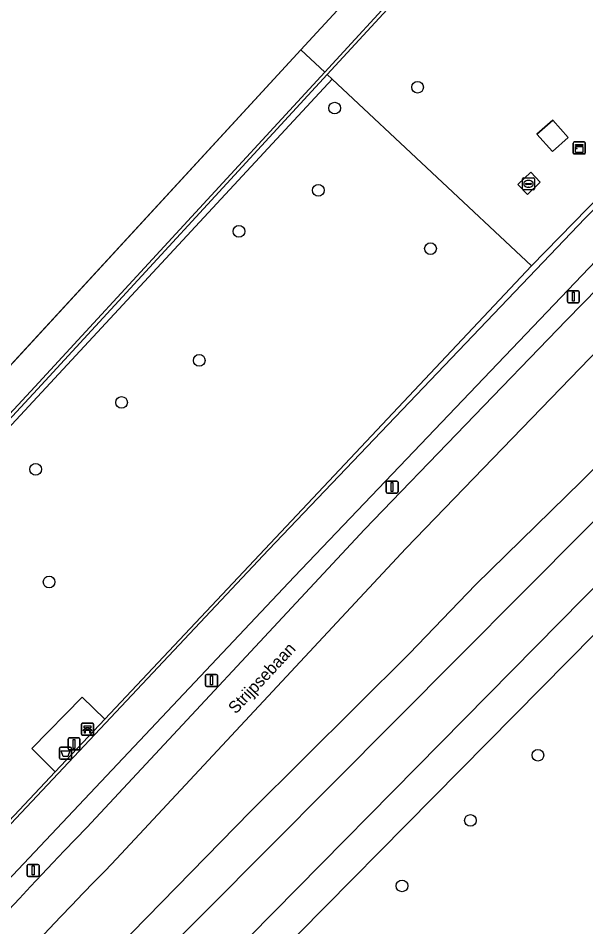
# Model space of a CAD drawing. Extents: x 155640 to 156811, y 382821 to 384049.
# Drawn here: x 156314.4 to 156361.8, y 383250.2 to 383326 of the extents above; entities that cross this region are included whole.
import ezdxf

# ---------------------------------------------------------------- set-up
doc = ezdxf.new("R2010")
doc.units = 0
for name, color, linetype in [('IMGEO_Afvalbak', 7, 'Continuous'), ('IMGEO_Bank', 7, 'Continuous'), ('IMGEO_Berm_groen', 7, 'Continuous'), ('IMGEO_Boom', 7, 'Continuous'), ('IMGEO_Fietspad_gesloten', 7, 'Continuous'), ('IMGEO_Groenvoorziening', 7, 'Continuous'), ('IMGEO_Haag', 7, 'Continuous'), ('IMGEO_Hek', 7, 'Continuous'), ('IMGEO_Kast', 7, 'Continuous'), ('IMGEO_Lichtmast', 7, 'Continuous'), ('IMGEO_Oever', 7, 'Continuous'), ('IMGEO_Openbare_ruimte_label', 7, 'Continuous'), ('IMGEO_Pand', 7, 'Continuous'), ('IMGEO_Rioolput', 7, 'Continuous'), ('IMGEO_Verkeersbordpaal', 7, 'Continuous'), ('IMGEO_Voetpad_gesloten', 7, 'Continuous'), ('IMGEO_Waterloop', 7, 'Continuous')]:
    doc.layers.add(name, color=color, linetype=linetype)

msp = doc.modelspace()

# ---------------------------------------------------------------- linework, layer by layer
at = {"layer": 'IMGEO_Afvalbak'}
for p, q in [((156317.874, 383264.249), (156317.874, 383265.049)), ((156317.874, 383265.049), (156317.874, 383264.249)), ((156317.974, 383265.149), (156318.764, 383265.149)), ((156318.764, 383265.149), (156317.974, 383265.149)), ((156318.864, 383265.049), (156318.864, 383264.249)), ((156318.864, 383264.249), (156318.864, 383265.049)), ((156318.764, 383264.149), (156317.974, 383264.149)), ((156317.974, 383264.149), (156318.764, 383264.149))]:
    msp.add_line(p, q, dxfattribs=at)
msp.add_lwpolyline([(156318.017, 383264.863), (156318.721, 383264.863), (156318.572, 383264.393), (156318.166, 383264.393), (156318.017, 383264.863)], dxfattribs=at)
for centre, start, end in [((156317.974, 383265.049), 90, 180), ((156317.974, 383265.049), 90, 180), ((156318.764, 383265.049), 0, 90), ((156318.764, 383265.049), 360, 90), ((156317.974, 383264.249), 180, 270), ((156317.974, 383264.249), 180, 270), ((156318.764, 383264.249), 270, 0), ((156318.764, 383264.249), 270, 0)]:
    msp.add_arc(centre, 0.1, start, end, dxfattribs=at)
at = {"layer": 'IMGEO_Bank'}
for p, q in [((156319.7, 383266.232), (156319.7, 383267.073)), ((156319.7, 383267.073), (156319.7, 383266.232)), ((156319.775, 383267.157), (156320.616, 383267.157)), ((156320.616, 383267.157), (156319.775, 383267.157)), ((156320.7, 383267.082), (156320.7, 383266.241)), ((156320.7, 383266.241), (156320.7, 383267.082)), ((156320.397, 383266.555), (156320.004, 383266.555)), ((156320.009, 383266.663), (156320.009, 383266.769)), ((156320.053, 383266.769), (156320.053, 383266.663)), ((156320.341, 383266.775), (156320.059, 383266.775)), ((156320.059, 383266.657), (156320.341, 383266.657)), ((156320.347, 383266.663), (156320.347, 383266.769)), ((156320.391, 383266.769), (156320.391, 383266.663)), ((156320.625, 383266.157), (156319.784, 383266.157)), ((156319.784, 383266.157), (156320.625, 383266.157))]:
    msp.add_line(p, q, dxfattribs=at)
for points in [[(156319.947, 383266.555), (156319.805, 383266.555), (156319.917, 383266.657), (156320.003, 383266.657)], [(156320.003, 383266.775), (156319.917, 383266.775), (156319.917, 383266.936), (156320.48, 383266.936), (156320.48, 383266.775), (156320.397, 383266.775)], [(156319.997, 383266.548), (156319.997, 383266.341), (156319.954, 383266.341), (156319.954, 383266.548)], [(156320.397, 383266.657), (156320.48, 383266.657), (156320.592, 383266.555), (156320.453, 383266.555)], [(156320.447, 383266.548), (156320.447, 383266.341), (156320.403, 383266.341), (156320.403, 383266.548)]]:
    msp.add_lwpolyline(points, dxfattribs=at)
for centre, radius, start, end in [((156319.778, 383267.079), 0.0779, 92.4484, 184.28452), ((156319.778, 383267.079), 0.0779, 92.4484, 184.28452), ((156320.622, 383267.079), 0.0779, 2.4484, 94.28452), ((156320.622, 383267.079), 0.0779, 2.4484, 94.28452), ((156319.947, 383266.548), 0.00671, 2.89567, 87.10433), ((156320.004, 383266.548), 0.00671, 92.89567, 177.10433), ((156320.002, 383266.768), 0.00671, 2.89567, 87.10433), ((156320.002, 383266.664), 0.00671, 272.89567, 357.10433), ((156320.059, 383266.768), 0.00671, 92.89567, 177.10433), ((156320.059, 383266.664), 0.00671, 182.89567, 267.10433), ((156320.341, 383266.768), 0.00671, 2.89567, 87.10433), ((156320.341, 383266.664), 0.00671, 272.89567, 357.10433), ((156320.398, 383266.768), 0.00671, 92.89567, 177.10433), ((156320.398, 383266.664), 0.00671, 182.89567, 267.10433), ((156320.396, 383266.548), 0.00671, 2.89567, 87.10433), ((156320.453, 383266.548), 0.00671, 92.89567, 177.10433), ((156319.778, 383266.235), 0.0779, 182.4484, 274.28452), ((156319.778, 383266.235), 0.0779, 182.4484, 274.28452), ((156320.622, 383266.235), 0.0779, 272.4484, 4.28452), ((156320.622, 383266.235), 0.0779, 272.4484, 4.28452)]:
    msp.add_arc(centre, radius, start, end, dxfattribs=at)
at = {"layer": 'IMGEO_Berm_groen'}
for points in [[(156381.892, 383325.599), (156381.348, 383325.039), (156380.959, 383324.639), (156363.82, 383307.004), (156337.443, 383279.37), (156311.15, 383251.521)], [(156360.181, 383300.803), (156380.194, 383321.217)], [(156373.432, 383309.293), (156346.778, 383281.729), (156322.635, 383255.833)], [(156320.142, 383258.454), (156343.328, 383283.312), (156360.181, 383300.803)], [(156233.027, 383113.173), (156252.866, 383146.34), (156268.602, 383172.647), (156299.809, 383224.819), (156307.157, 383232.786), (156316.472, 383242.07), (156333.801, 383259.79), (156347.065, 383272.962), (156352.588, 383278.703), (156361.434, 383287.344), (156366.724, 383292.604)]]:
    msp.add_lwpolyline(points, dxfattribs=at)
for centre, radius, start, end in [((156587.608, 382998.357), 373.08, 135.80033, 142.47889), ((156555.245, 383025.413), 327.415, 135.27102, 142.78641)]:
    msp.add_arc(centre, radius, start, end, dxfattribs=at)
at = {"layer": 'IMGEO_Boom'}
for centre in [(156347.751, 383320.225), (156340.835, 383318.484), (156339.472, 383311.623), (156332.842, 383308.2), (156348.832, 383306.757), (156329.527, 383297.433), (156323.046, 383293.927), (156315.877, 383288.344), (156316.998, 383278.946), (156357.798, 383264.485), (156352.165, 383259.047), (156346.453, 383253.585)]:
    msp.add_circle(centre, 0.489, dxfattribs=at)
at = {"layer": 'IMGEO_Fietspad_gesloten'}
for points in [[(156380.194, 383321.217), (156360.181, 383300.803), (156343.328, 383283.312), (156320.142, 383258.454)], [(156322.635, 383255.833), (156346.778, 383281.729), (156373.432, 383309.293), (156378.108, 383314.02)]]:
    msp.add_lwpolyline(points, dxfattribs=at)
for centre, radius, start, end in [((156587.608, 382998.357), 373.08, 135.80033, 142.47889), ((156555.245, 383025.413), 327.415, 135.27102, 142.78641)]:
    msp.add_arc(centre, radius, start, end, dxfattribs=at)
at = {"layer": 'IMGEO_Groenvoorziening'}
for points in [[(156307.679, 383394.347), (156302.123, 383400.705), (156299.359, 383400.927), (156306.65, 383393.611), (156313.765, 383385.402), (156329.371, 383369.364), (156360.098, 383342.127), (156366.667, 383336.304), (156365.54, 383332.038), (156365.287, 383328.46), (156365.66, 383324.427), (156366.576, 383319.504), (156367.747, 383316.069), (156357.254, 383305.321), (156321.635, 383267.495), (156317.51, 383263.114), (156305.054, 383249.887), (156299.88, 383244.1), (156294.909, 383238.207), (156290.182, 383232.037), (156285.682, 383225.699), (156281.371, 383219.262), (156269.6, 383231.099)], [(156308.935, 383253.615), (156335.323, 383281.619), (156361.745, 383309.309), (156379.48, 383327.364), (156380.013, 383327.906), (156380.504, 383328.406), (156379.648, 383329.081), (156379.009, 383329.585), (156369.095, 383337.403), (156363.724, 383341.638)], [(156288.244, 383328.729), (156283.659, 383323.836), (156299.584, 383309.177), (156312.986, 383296.711), (156312.61, 383296.315), (156309.263, 383292.789), (156309.574, 383292.506), (156338.016, 383323.341), (156350.486, 383336.861)], [(156346.883, 383328.534), (156340.219, 383321.277), (156340.634, 383320.888), (156357.254, 383305.321), (156367.747, 383316.069), (156366.576, 383319.504), (156365.66, 383324.427), (156365.287, 383328.46)], [(156269.6, 383231.099), (156263.233, 383237.503), (156340.634, 383320.888), (156340.219, 383321.277), (156316.032, 383295.022), (156259.545, 383234.109), (156254.254, 383228.85), (156241.376, 383245.741), (156226.676, 383261.562), (156226.145, 383261.011), (156229.047, 383257.84)], [(156401.917, 383275.179), (156387.41, 383302.346), (156381.815, 383296.443), (156381.713, 383295.875), (156381.067, 383294.349), (156380.037, 383292.488), (156379.109, 383291.061), (156378.013, 383290.134), (156376.603, 383288.823), (156373.814, 383286.022), (156313.066, 383224.543), (156307.199, 383217.739), (156241.776, 383106.748)]]:
    msp.add_lwpolyline(points, dxfattribs=at)
for points in [[(156303.92, 383385.489), (156304.175, 383385.733), (156292.088, 383397.03), (156288.952, 383393.961), (156316.643, 383368.447), (156350.486, 383336.861), (156338.016, 383323.341), (156340, 383321.482), (156346.651, 383328.741), (156354.938, 383337.785), (156351.749, 383340.767)], [(156340.219, 383321.277), (156346.883, 383328.534), (156346.651, 383328.741), (156340, 383321.482), (156315.812, 383295.226), (156259.528, 383234.533), (156235.771, 383256.436), (156228.393, 383263.345), (156228.185, 383263.129), (156235.566, 383256.217), (156259.545, 383234.109), (156316.032, 383295.022)], [(156315.812, 383295.226), (156340, 383321.482), (156338.016, 383323.341), (156309.574, 383292.506), (156309.479, 383292.403), (156307.563, 383290.326), (156286.105, 383267.166), (156285.653, 383266.679), (156282.79, 383263.589), (156259.014, 383237.928), (156232.367, 383263.357), (156230.326, 383265.146), (156230.078, 383264.903), (156229.968, 383265.006), (156229.248, 383264.232), (156228.393, 383263.345), (156235.771, 383256.436), (156259.528, 383234.533)], [(156321.635, 383267.495), (156357.254, 383305.321), (156340.634, 383320.888), (156263.233, 383237.503), (156269.6, 383231.099), (156281.371, 383219.262), (156285.682, 383225.699), (156290.182, 383232.037), (156294.909, 383238.207), (156299.88, 383244.1), (156305.054, 383249.887), (156317.51, 383263.114), (156315.563, 383265.05), (156319.758, 383269.341)], [(156359.03, 383317.477), (156360.316, 383316.034), (156359.003, 383314.864), (156357.717, 383316.307)], [(156357.2, 383313.134), (156357.996, 383312.308), (156356.925, 383311.275), (156356.129, 383312.101)]]:
    msp.add_lwpolyline(points, close=True, dxfattribs=at)
at = {"layer": 'IMGEO_Haag'}
msp.add_lwpolyline([(156340.219, 383321.277), (156346.883, 383328.534), (156346.651, 383328.741), (156340, 383321.482), (156315.812, 383295.226), (156259.528, 383234.533), (156235.771, 383256.436), (156228.393, 383263.345), (156228.185, 383263.129), (156235.566, 383256.217), (156259.545, 383234.109), (156316.032, 383295.022)], close=True, dxfattribs=at)
at = {"layer": 'IMGEO_Hek'}
for points in [[(156284.232, 383388.919), (156288.952, 383393.961), (156316.643, 383368.447), (156350.486, 383336.861), (156338.016, 383323.341)], [(156338.016, 383323.341), (156309.479, 383292.403)], [(156340.634, 383320.888), (156263.233, 383237.503), (156269.6, 383231.099)], [(156357.254, 383305.321), (156340.634, 383320.888)], [(156281.371, 383219.262), (156285.682, 383225.699), (156290.182, 383232.037), (156294.909, 383238.207), (156299.88, 383244.1), (156305.054, 383249.887), (156317.51, 383263.114), (156321.635, 383267.495), (156357.254, 383305.321)]]:
    msp.add_lwpolyline(points, dxfattribs=at)
at = {"layer": 'IMGEO_Kast'}
for p, q in [((156360.752, 383314.731), (156360.752, 383315.572)), ((156360.752, 383315.572), (156360.752, 383314.731)), ((156360.827, 383315.656), (156361.668, 383315.656)), ((156361.668, 383315.656), (156360.827, 383315.656)), ((156361.752, 383315.581), (156361.752, 383314.74)), ((156361.752, 383314.74), (156361.752, 383315.581)), ((156361.677, 383314.656), (156360.836, 383314.656)), ((156360.836, 383314.656), (156361.677, 383314.656))]:
    msp.add_line(p, q, dxfattribs=at)
for points in [[(156360.947, 383315.446), (156361.547, 383315.446), (156361.547, 383315.361), (156360.947, 383315.361), (156360.947, 383315.446)], [(156360.947, 383315.271), (156361.547, 383315.271), (156361.547, 383314.782), (156360.947, 383314.782), (156360.947, 383315.271)]]:
    msp.add_lwpolyline(points, dxfattribs=at)
msp.add_circle((156361.031, 383315.12), 0.0377, dxfattribs=at)
for centre, start, end in [((156360.83, 383315.578), 92.4484, 184.28452), ((156360.83, 383315.578), 92.4484, 184.28452), ((156361.674, 383315.578), 2.4484, 94.28452), ((156361.674, 383315.578), 2.4484, 94.28452), ((156360.83, 383314.734), 182.4484, 274.28452), ((156360.83, 383314.734), 182.4484, 274.28452), ((156361.674, 383314.734), 272.4484, 4.28452), ((156361.674, 383314.734), 272.4484, 4.28452)]:
    msp.add_arc(centre, 0.0779, start, end, dxfattribs=at)
at = {"layer": 'IMGEO_Lichtmast'}
for p, q in [((156360.257, 383302.345), (156360.257, 383303.145)), ((156360.257, 383303.145), (156360.257, 383302.345)), ((156360.357, 383303.245), (156361.147, 383303.245)), ((156361.147, 383303.245), (156360.357, 383303.245)), ((156361.247, 383303.145), (156361.247, 383302.345)), ((156361.247, 383302.345), (156361.247, 383303.145)), ((156361.147, 383302.245), (156360.357, 383302.245)), ((156360.357, 383302.245), (156361.147, 383302.245)), ((156345.129, 383286.465), (156345.129, 383287.265)), ((156345.129, 383287.265), (156345.129, 383286.465)), ((156345.229, 383287.365), (156346.019, 383287.365)), ((156346.019, 383287.365), (156345.229, 383287.365)), ((156346.119, 383287.265), (156346.119, 383286.465)), ((156346.119, 383286.465), (156346.119, 383287.265)), ((156346.019, 383286.365), (156345.229, 383286.365)), ((156345.229, 383286.365), (156346.019, 383286.365)), ((156330.054, 383270.332), (156330.054, 383271.132)), ((156330.054, 383271.132), (156330.054, 383270.332)), ((156330.154, 383271.232), (156330.944, 383271.232)), ((156330.944, 383271.232), (156330.154, 383271.232)), ((156331.044, 383271.132), (156331.044, 383270.332)), ((156331.044, 383270.332), (156331.044, 383271.132)), ((156330.944, 383270.232), (156330.154, 383270.232)), ((156330.154, 383270.232), (156330.944, 383270.232)), ((156315.17, 383254.475), (156315.17, 383255.275)), ((156315.17, 383255.275), (156315.17, 383254.475)), ((156315.27, 383255.375), (156316.06, 383255.375)), ((156316.06, 383255.375), (156315.27, 383255.375)), ((156316.16, 383255.275), (156316.16, 383254.475)), ((156316.16, 383254.475), (156316.16, 383255.275)), ((156316.06, 383254.375), (156315.27, 383254.375)), ((156315.27, 383254.375), (156316.06, 383254.375))]:
    msp.add_line(p, q, dxfattribs=at)
for points in [[(156360.677, 383303.12), (156360.827, 383303.12), (156360.827, 383302.37), (156360.677, 383302.37), (156360.677, 383303.12)], [(156345.549, 383287.24), (156345.699, 383287.24), (156345.699, 383286.49), (156345.549, 383286.49), (156345.549, 383287.24)], [(156330.474, 383271.107), (156330.624, 383271.107), (156330.624, 383270.357), (156330.474, 383270.357), (156330.474, 383271.107)], [(156315.59, 383255.25), (156315.74, 383255.25), (156315.74, 383254.5), (156315.59, 383254.5), (156315.59, 383255.25)]]:
    msp.add_lwpolyline(points, dxfattribs=at)
for centre, start, end in [((156360.357, 383303.145), 90, 180), ((156360.357, 383303.145), 90, 180), ((156361.147, 383303.145), 0, 90), ((156361.147, 383303.145), 360, 90), ((156360.357, 383302.345), 180, 270), ((156360.357, 383302.345), 180, 270), ((156361.147, 383302.345), 270, 0), ((156361.147, 383302.345), 270, 0), ((156345.229, 383287.265), 90, 180), ((156345.229, 383287.265), 90, 180), ((156346.019, 383287.265), 0, 90), ((156346.019, 383287.265), 360, 90), ((156345.229, 383286.465), 180, 270), ((156345.229, 383286.465), 180, 270), ((156346.019, 383286.465), 270, 0), ((156346.019, 383286.465), 270, 0), ((156330.154, 383271.132), 90, 180), ((156330.154, 383271.132), 90, 180), ((156330.944, 383271.132), 0, 90), ((156330.944, 383271.132), 360, 90), ((156330.154, 383270.332), 180, 270), ((156330.154, 383270.332), 180, 270), ((156330.944, 383270.332), 270, 0), ((156330.944, 383270.332), 270, 0), ((156315.27, 383255.275), 90, 180), ((156315.27, 383255.275), 90, 180), ((156316.06, 383255.275), 0, 90), ((156316.06, 383255.275), 360, 90), ((156315.27, 383254.475), 180, 270), ((156315.27, 383254.475), 180, 270), ((156316.06, 383254.475), 270, 0), ((156316.06, 383254.475), 270, 0)]:
    msp.add_arc(centre, 0.1, start, end, dxfattribs=at)
at = {"layer": 'IMGEO_Oever'}
for points in [[(156314.169, 383235.475), (156377.724, 383299.338), (156379.347, 383298.182), (156375.527, 383291.728), (156309.837, 383225.147)], [(156366.724, 383292.604), (156361.434, 383287.344), (156352.588, 383278.703), (156347.065, 383272.962), (156333.801, 383259.79), (156316.472, 383242.07), (156307.157, 383232.786), (156299.809, 383224.819), (156268.602, 383172.647), (156252.866, 383146.34), (156233.027, 383113.173)], [(156241.776, 383106.748), (156307.199, 383217.739), (156313.066, 383224.543), (156373.814, 383286.022)]]:
    msp.add_lwpolyline(points, dxfattribs=at)
at = {"layer": 'IMGEO_Pand'}
msp.add_lwpolyline([(156359.003, 383314.864), (156360.316, 383316.034), (156359.03, 383317.477), (156357.717, 383316.307)], close=True, dxfattribs=at)
at = {"layer": 'IMGEO_Rioolput'}
for p, q in [((156356.51, 383311.735), (156356.51, 383312.587)), ((156356.585, 383312.661), (156357.437, 383312.661)), ((156357.511, 383312.587), (156357.511, 383311.735)), ((156356.769, 383312.155), (156356.769, 383312.167)), ((156357.207, 383312.118), (156356.809, 383312.118)), ((156356.812, 383312.204), (156357.21, 383312.204)), ((156357.021, 383311.881), (156356.996, 383311.881)), ((156356.998, 383312.441), (156357.023, 383312.441)), ((156357.253, 383312.167), (156357.253, 383312.155)), ((156357.437, 383311.661), (156356.585, 383311.661))]:
    msp.add_line(p, q, dxfattribs=at)
for points in [[(156356.51, 383311.735), (156356.51, 383312.587)], [(156356.585, 383312.661), (156357.437, 383312.661)], [(156357.511, 383312.587), (156357.511, 383311.735)], [(156357.437, 383311.661), (156356.585, 383311.661)]]:
    msp.add_lwpolyline(points, dxfattribs=at)
for centre, radius, start, end in [((156356.587, 383312.585), 0.0765, 91.55205, 178.44795), ((156356.587, 383312.585), 0.0765, 91.55205, 178.44795), ((156357.435, 383312.585), 0.0765, 1.55205, 88.44795), ((156357.435, 383312.585), 0.0765, 1.55205, 88.44795), ((156356.809, 383312.164), 0.0403, 85.87752, 175.75265), ((156356.806, 383312.154), 0.0366, 178.93798, 274.71019), ((156357.21, 383312.161), 0.043, 264.86636, 352.45326), ((156357.214, 383312.166), 0.0386, 1.73085, 96.63898), ((156356.587, 383311.737), 0.0765, 181.55205, 268.44795), ((156356.587, 383311.737), 0.0765, 181.55205, 268.44795), ((156357.435, 383311.737), 0.0765, 271.55205, 358.44795), ((156357.435, 383311.737), 0.0765, 271.55205, 358.44795)]:
    msp.add_arc(centre, radius, start, end, dxfattribs=at)
for centre, major_axis, ratio, start_param, end_param in [((156356.997, 383312.161), (-0.387, 0.002), 0.722429, 4.712389, 7.853982), ((156357.022, 383312.161), (-0.39, 0.002), 0.717154, 1.570796, 4.712389)]:
    msp.add_ellipse(centre, major_axis=major_axis, ratio=ratio, start_param=start_param, end_param=end_param, dxfattribs=at)
at = {"layer": 'IMGEO_Verkeersbordpaal'}
for p, q in [((156318.583, 383265.036), (156318.583, 383265.836)), ((156318.583, 383265.836), (156318.583, 383265.036)), ((156318.683, 383265.936), (156319.473, 383265.936)), ((156319.473, 383265.936), (156318.683, 383265.936)), ((156319.573, 383265.836), (156319.573, 383265.036)), ((156319.573, 383265.036), (156319.573, 383265.836)), ((156319.473, 383264.936), (156318.683, 383264.936)), ((156318.683, 383264.936), (156319.473, 383264.936))]:
    msp.add_line(p, q, dxfattribs=at)
msp.add_lwpolyline([(156319.003, 383265.811), (156319.153, 383265.811), (156319.153, 383265.061), (156319.003, 383265.061), (156319.003, 383265.811)], dxfattribs=at)
for centre, start, end in [((156318.683, 383265.836), 90, 180), ((156318.683, 383265.836), 90, 180), ((156319.473, 383265.836), 0, 90), ((156319.473, 383265.836), 360, 90), ((156318.683, 383265.036), 180, 270), ((156318.683, 383265.036), 180, 270), ((156319.473, 383265.036), 270, 0), ((156319.473, 383265.036), 270, 0)]:
    msp.add_arc(centre, 0.1, start, end, dxfattribs=at)
at = {"layer": 'IMGEO_Voetpad_gesloten'}
for points in [[(156380.504, 383328.406), (156380.013, 383327.906), (156379.48, 383327.364), (156361.745, 383309.309), (156335.323, 383281.619), (156308.935, 383253.615)], [(156337.443, 383279.37), (156363.82, 383307.004), (156380.959, 383324.639), (156381.348, 383325.039), (156381.892, 383325.599)], [(156311.15, 383251.521), (156337.443, 383279.37)]]:
    msp.add_lwpolyline(points, dxfattribs=at)
for points in [[(156356.925, 383311.275), (156357.996, 383312.308), (156357.2, 383313.134), (156356.129, 383312.101)], [(156321.635, 383267.495), (156319.758, 383269.341), (156315.563, 383265.05), (156317.51, 383263.114)]]:
    msp.add_lwpolyline(points, close=True, dxfattribs=at)
at = {"layer": 'IMGEO_Waterloop'}
msp.add_lwpolyline([(156309.837, 383225.147), (156375.527, 383291.728), (156379.347, 383298.182), (156377.724, 383299.338), (156314.169, 383235.475)], dxfattribs=at)

# ---------------------------------------------------------------- texts
at = {"layer": 'IMGEO_Openbare_ruimte_label'}
msp.add_text('Strijpsebaan', height=1, rotation=46.98611, dxfattribs=at).set_placement((156332.577, 383267.873))

doc.saveas('drawing.dxf')
